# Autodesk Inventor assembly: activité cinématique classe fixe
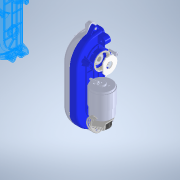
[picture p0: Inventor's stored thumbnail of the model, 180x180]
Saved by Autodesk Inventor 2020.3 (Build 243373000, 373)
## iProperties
Created: 2020-11
Part Number: activité cinématique classe fixe
Document SubType Name: Assembly
Designer: ficho
Mass: 1737.49 g
Surface Area: 18261.2 cm^2
Volume: 1638.89 cm^3
Density: 1.06016 g/cm^3
Author: ficho
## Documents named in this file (5)
- D:\travail\année 2020-2021\2I2D\laveur de vitre\Lave vitre\4 Dossier Ressources\1 Modèles 3D Solidworks\activité cinématique classe fixe.iam
- D:\travail\année 2020-2021\2I2D\laveur de vitre\Lave vitre\4 Dossier Ressources\1 Modèles 3D Solidworks\classe fixe.iam
- D:\travail\année 2020-2021\2I2D\laveur de vitre\Lave vitre\4 Dossier Ressources\1 Modèles 3D Solidworks\Demi-capot chenille moteur inventor.ipt
- D:\travail\année 2020-2021\2I2D\laveur de vitre\Lave vitre\4 Dossier Ressources\1 Modèles 3D Solidworks\Demi-capot chenille inventor.ipt
- D:\travail\année 2020-2021\2I2D\laveur de vitre\Lave vitre\4 Dossier Ressources\1 Modèles 3D Solidworks\roulement capot chenille.ipt
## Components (6 placed, 4 different names)
1. classe fixe:1 [sub-assembly] — Placage:6, Logement:42
2. Demi-capot chenille moteur inventor:1 — Placage:6, Logement:42, Logement:43, Logement:51, Angle:1
3. Demi-capot chenille inventor:1 — Logement:48, Logement:49, Logement:51, Angle:1
4. roulement capot chenille:2 — Logement:49
5. roulement capot chenille:3 — Logement:43
6. roulement capot chenille:4 — Logement:48
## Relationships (7: Insert 5, Mate 1, Angle 1)
- Placage:6 [Mate]: classe fixe:1 ↔ Demi-capot chenille moteur inventor:1
- Logement:42 [Insert]: classe fixe:1 ↔ Demi-capot chenille moteur inventor:1
- Logement:43 [Insert]: Demi-capot chenille moteur inventor:1 ↔ roulement capot chenille:3
- Logement:48 [Insert]: Demi-capot chenille inventor:1 ↔ roulement capot chenille:4
- Logement:49 [Insert]: Demi-capot chenille inventor:1 ↔ roulement capot chenille:2
- Logement:51 [Insert]: Demi-capot chenille moteur inventor:1 ↔ Demi-capot chenille inventor:1
- Angle:1: Demi-capot chenille moteur inventor:1 ↔ Demi-capot chenille inventor:1
